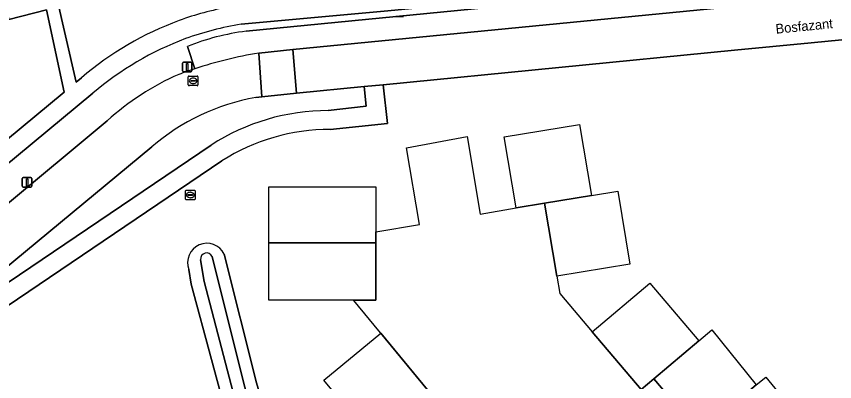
# Model space of a CAD drawing. Extents: x 156661 to 157576, y 383570 to 384425.
# Drawn here: x 156830 to 156914.8, y 383880.2 to 383918.1 of the extents above; entities that cross this region are included whole.
import ezdxf

# ---------------------------------------------------------------- set-up
doc = ezdxf.new("R2010")
doc.units = 0
for name, color, linetype in [('IMGEO_Berm_groen', 7, 'Continuous'), ('IMGEO_Groenvoorziening', 7, 'Continuous'), ('IMGEO_Lichtmast', 7, 'Continuous'), ('IMGEO_Oever', 7, 'Continuous'), ('IMGEO_Openbare_ruimte_label', 7, 'Continuous'), ('IMGEO_Pand_vergunning_verleend', 7, 'Continuous'), ('IMGEO_Parkeervlak_open', 7, 'Continuous'), ('IMGEO_Rijbaan_lokaal_open', 7, 'Continuous'), ('IMGEO_Rioolput', 7, 'Continuous'), ('IMGEO_Voetpad_gesloten', 7, 'Continuous'), ('IMGEO_Voetpad_open', 7, 'Continuous'), ('IMGEO_Waterloop', 7, 'Continuous')]:
    doc.layers.add(name, color=color, linetype=linetype)

msp = doc.modelspace()

# ---------------------------------------------------------------- linework, layer by layer
at = {"layer": 'IMGEO_Berm_groen'}
for points in [[(156853.805, 383916.581), (156939.653, 383925.02), (156939.883, 383922.625), (156942.261, 383922.858), (156942.029, 383925.893), (156868.496, 383918.711), (156853.282, 383917.324)], [(156848.489, 383912.685), (156847.704, 383914.986)], [(156862.309, 383908.349), (156866.252, 383908.792), (156866.027, 383910.844), (156859.004, 383910.155), (156855.44, 383909.783), (156854.801, 383909.693)], [(156837.91, 383910.165), (156822.254, 383897.18)], [(156828.657, 383898.337), (156839.395, 383907.281)], [(156819.797, 383884.223), (156850.165, 383904.772)], [(156844.018, 383904.581), (156820.237, 383884.885)]]:
    msp.add_lwpolyline(points, dxfattribs=at)
for centre, radius, start, end in [((156859.222, 383882.929), 34.904, 99.79783, 109.59833), ((156858.999, 383885.284), 32.616, 110.61694, 130.2839), ((156856.823, 383892.571), 24.199, 97.16439, 112.13775), ((156862.742, 383869.358), 45.611, 108.20873, 110.4265), ((156857.829, 383887.006), 27.403, 113.68148, 132.27728), ((156858.547, 383887.863), 22.149, 99.73687, 130.99248), ((156862.297, 383885.988), 22.361, 89.96818, 122.85636)]:
    msp.add_arc(centre, radius, start, end, dxfattribs=at)
at = {"layer": 'IMGEO_Groenvoorziening'}
for points in [[(156823.818, 383940.987), (156833.736, 383943.193), (156833.955, 383942.205), (156836.909, 383942.836), (156838.218, 383936.976), (156838.514, 383935.647), (156839.821, 383929.794), (156840.117, 383928.468), (156841.425, 383922.608), (156839.83, 383922.252), (156839.933, 383921.788), (156834.083, 383920.486), (156836.167, 383911.298), (156836.719, 383911.755)], [(156960.429, 383920.102), (156912.352, 383915.387), (156904.417, 383914.609), (156867.996, 383911.037), (156868.437, 383907.016), (156862.509, 383906.391)], [(156820.131, 383898.001), (156834.922, 383910.265), (156833.107, 383918.804), (156829.202, 383917.794), (156823.434, 383916.512), (156820.398, 383915.844), (156817.468, 383915.2), (156816.817, 383918.128), (156816.732, 383918.51), (156810.873, 383917.164), (156812.023, 383911.93), (156814.996, 383912.584), (156815.273, 383911.078), (156812.396, 383910.435), (156812.552, 383909.758)], [(156851.293, 383903.131), (156818.935, 383881.258)], [(156851.524, 383893.461), (156854.87, 383880.095), (156855.954, 383876.481), (156875.133, 383855.234), (156891.457, 383836.513), (156911.625, 383812.792), (156912.799, 383811.318), (156913.716, 383811.623), (156932.366, 383827.967), (156950.379, 383842.94), (156962.3, 383852.372), (156962.639, 383852.867), (156967.115, 383858.578), (156983.419, 383879.381)], [(156930.606, 383784.803), (156881.087, 383841.394), (156853.843, 383872.65), (156852.3, 383874.708), (156848.113, 383890.33), (156847.869, 383891.869)]]:
    msp.add_lwpolyline(points, dxfattribs=at)
for centre, radius, start, end in [((156857.204, 383889.617), 29.92, 100.03858, 110.20436), ((156858.538, 383886.116), 33.666, 110.27555, 130.39721), ((156862.399, 383885.846), 20.545, 89.69244, 122.72123), ((156849.728, 383892.592), 1.995, 25.82674, 201.24604)]:
    msp.add_arc(centre, radius, start, end, dxfattribs=at)
at = {"layer": 'IMGEO_Lichtmast'}
for p, q in [((156870.101, 383918.123), (156869.311, 383918.123)), ((156869.311, 383918.123), (156870.101, 383918.123)), ((156847.19, 383912.458), (156847.19, 383913.258)), ((156847.19, 383913.258), (156847.19, 383912.458)), ((156847.29, 383913.358), (156848.08, 383913.358)), ((156848.08, 383913.358), (156847.29, 383913.358)), ((156848.18, 383913.258), (156848.18, 383912.458)), ((156848.18, 383912.458), (156848.18, 383913.258)), ((156848.08, 383912.358), (156847.29, 383912.358)), ((156847.29, 383912.358), (156848.08, 383912.358)), ((156830.701, 383901.394), (156831.491, 383901.394)), ((156831.491, 383901.394), (156830.701, 383901.394)), ((156830.601, 383900.494), (156830.601, 383901.294)), ((156830.601, 383901.294), (156830.601, 383900.494)), ((156831.591, 383901.294), (156831.591, 383900.494)), ((156831.591, 383900.494), (156831.591, 383901.294)), ((156831.491, 383900.394), (156830.701, 383900.394)), ((156830.701, 383900.394), (156831.491, 383900.394))]:
    msp.add_line(p, q, dxfattribs=at)
for points in [[(156847.61, 383913.233), (156847.76, 383913.233), (156847.76, 383912.483), (156847.61, 383912.483), (156847.61, 383913.233)], [(156831.021, 383901.269), (156831.171, 383901.269), (156831.171, 383900.519), (156831.021, 383900.519), (156831.021, 383901.269)]]:
    msp.add_lwpolyline(points, dxfattribs=at)
for centre, start, end in [((156847.29, 383913.258), 90, 180), ((156847.29, 383913.258), 90, 180), ((156848.08, 383913.258), 0, 90), ((156848.08, 383913.258), 360, 90), ((156847.29, 383912.458), 180, 270), ((156847.29, 383912.458), 180, 270), ((156848.08, 383912.458), 270, 0), ((156848.08, 383912.458), 270, 0), ((156830.701, 383901.294), 90, 180), ((156830.701, 383901.294), 90, 180), ((156831.491, 383901.294), 0, 90), ((156831.491, 383901.294), 360, 90), ((156830.701, 383900.494), 180, 270), ((156830.701, 383900.494), 180, 270), ((156831.491, 383900.494), 270, 0), ((156831.491, 383900.494), 270, 0)]:
    msp.add_arc(centre, 0.1, start, end, dxfattribs=at)
at = {"layer": 'IMGEO_Oever'}
for points in [[(156931.624, 383785.153), (156882.046, 383842.232), (156854.834, 383873.451), (156853.466, 383875.275), (156849.461, 383890.631), (156849.071, 383892.878)], [(156850.277, 383893.203), (156853.642, 383879.757), (156854.817, 383875.841), (156874.18, 383854.389), (156890.492, 383835.682), (156910.642, 383811.983), (156912.357, 383809.829), (156914.362, 383810.496), (156933.193, 383826.998), (156951.181, 383841.951), (156963.242, 383851.493), (156963.694, 383852.153)], [(156983.419, 383879.381), (156967.115, 383858.578), (156962.639, 383852.867), (156962.3, 383852.372), (156950.379, 383842.94), (156932.366, 383827.967), (156913.716, 383811.623), (156912.799, 383811.318), (156911.625, 383812.792), (156891.457, 383836.513), (156875.133, 383855.234), (156855.954, 383876.481), (156854.87, 383880.095), (156851.524, 383893.461)], [(156847.869, 383891.869), (156848.113, 383890.33), (156852.3, 383874.708), (156853.843, 383872.65), (156881.087, 383841.394), (156930.606, 383784.803)]]:
    msp.add_lwpolyline(points, dxfattribs=at)
for centre, radius, start, end in [((156849.728, 383892.592), 1.995, 25.82674, 201.24604), ((156849.698, 383892.95), 0.631, 23.60093, 186.56331)]:
    msp.add_arc(centre, radius, start, end, dxfattribs=at)
at = {"layer": 'IMGEO_Pand_vergunning_verleend'}
for points in [[(156889.575, 383899.545), (156884.73, 383898.741), (156881.774, 383898.251), (156880.551, 383905.617), (156888.353, 383906.912)], [(156867.243, 383894.637), (156856.147, 383894.637), (156856.147, 383900.425), (156867.243, 383900.425)], [(156884.73, 383898.741), (156889.575, 383899.545), (156892.303, 383899.998), (156893.56, 383892.425), (156885.987, 383891.168)], [(156856.147, 383894.637), (156867.243, 383894.637), (156867.243, 383888.675), (156856.147, 383888.675)], [(156900.701, 383884.465), (156896.064, 383880.542), (156894.724, 383879.407), (156889.666, 383885.384), (156895.643, 383890.442)], [(156872.604, 383879.4), (156866.718, 383874.494), (156861.852, 383880.383), (156867.759, 383885.264)], [(156906.666, 383879.89), (156900.827, 383874.914), (156896.064, 383880.542), (156900.701, 383884.465), (156902.046, 383885.604)], [(156909.131, 383874.358), (156903.349, 383869.308), (156899.532, 383873.818), (156900.827, 383874.914), (156906.666, 383879.89), (156907.672, 383880.703), (156911.35, 383876.152)]]:
    msp.add_lwpolyline(points, close=True, dxfattribs=at)
msp.add_lwpolyline([(156872.604, 383879.4), (156864.962, 383888.649), (156867.243, 383888.675), (156867.243, 383895.764), (156871.762, 383896.537), (156870.401, 383904.492), (156876.696, 383905.65), (156878.055, 383897.614), (156881.774, 383898.251), (156884.73, 383898.741), (156885.987, 383891.168), (156886.292, 383889.368), (156889.666, 383885.384), (156894.724, 383879.407), (156896.064, 383880.542), (156900.827, 383874.914)], dxfattribs=at)
at = {"layer": 'IMGEO_Parkeervlak_open'}
for points in [[(156855.097, 383914.318), (156858.629, 383914.671), (156939.883, 383922.625), (156939.653, 383925.02), (156853.805, 383916.581)], [(156847.704, 383914.986), (156848.489, 383912.685)]]:
    msp.add_lwpolyline(points, dxfattribs=at)
for centre, radius, start, end in [((156856.823, 383892.571), 24.199, 97.16439, 112.13775), ((156862.607, 383869.742), 45.204, 99.56326, 108.19892)]:
    msp.add_arc(centre, radius, start, end, dxfattribs=at)
at = {"layer": 'IMGEO_Rijbaan_lokaal_open'}
for points in [[(156970.285, 383925.601), (156957.067, 383924.307), (156955.199, 383924.125), (156952.527, 383923.863), (156946.775, 383923.3), (156944.299, 383923.058), (156942.261, 383922.858), (156939.883, 383922.625), (156858.629, 383914.671), (156859.004, 383910.155), (156866.027, 383910.844), (156867.996, 383911.037), (156904.417, 383914.609), (156912.352, 383915.387), (156960.429, 383920.102)], [(156854.801, 383909.693), (156855.44, 383909.783), (156855.097, 383914.318)], [(156839.395, 383907.281), (156828.657, 383898.337), (156814.301, 383887.284), (156819.797, 383884.223)], [(156820.237, 383884.885), (156844.018, 383904.581)]]:
    msp.add_lwpolyline(points, dxfattribs=at)
msp.add_lwpolyline([(156855.44, 383909.783), (156859.004, 383910.155), (156858.629, 383914.671), (156855.097, 383914.318)], close=True, dxfattribs=at)
for centre, radius, start, end in [((156862.607, 383869.742), 45.204, 99.56326, 108.19892), ((156862.742, 383869.358), 45.611, 108.20873, 110.4265), ((156857.829, 383887.006), 27.403, 113.68148, 132.27728), ((156858.547, 383887.863), 22.149, 99.73687, 130.99248)]:
    msp.add_arc(centre, radius, start, end, dxfattribs=at)
at = {"layer": 'IMGEO_Rioolput'}
for p, q in [((156847.802, 383911.008), (156847.802, 383911.86)), ((156847.877, 383911.934), (156848.729, 383911.934)), ((156848.29, 383911.714), (156848.315, 383911.714)), ((156848.803, 383911.86), (156848.803, 383911.008)), ((156848.729, 383910.934), (156847.877, 383910.934)), ((156848.061, 383911.428), (156848.061, 383911.44)), ((156848.499, 383911.391), (156848.101, 383911.391)), ((156848.104, 383911.477), (156848.502, 383911.477)), ((156848.313, 383911.154), (156848.288, 383911.154)), ((156848.545, 383911.44), (156848.545, 383911.428)), ((156847.511, 383899.167), (156847.511, 383900.019)), ((156847.586, 383900.093), (156848.438, 383900.093)), ((156847.999, 383899.873), (156848.024, 383899.873)), ((156848.512, 383900.019), (156848.512, 383899.167)), ((156848.438, 383899.093), (156847.586, 383899.093)), ((156847.77, 383899.587), (156847.77, 383899.599)), ((156848.208, 383899.55), (156847.81, 383899.55)), ((156847.813, 383899.636), (156848.211, 383899.636)), ((156848.022, 383899.313), (156847.997, 383899.313)), ((156848.254, 383899.599), (156848.254, 383899.587))]:
    msp.add_line(p, q, dxfattribs=at)
for points in [[(156847.802, 383911.008), (156847.802, 383911.86)], [(156847.877, 383911.934), (156848.729, 383911.934)], [(156848.803, 383911.86), (156848.803, 383911.008)], [(156848.729, 383910.934), (156847.877, 383910.934)], [(156847.511, 383899.167), (156847.511, 383900.019)], [(156847.586, 383900.093), (156848.438, 383900.093)], [(156848.512, 383900.019), (156848.512, 383899.167)], [(156848.438, 383899.093), (156847.586, 383899.093)]]:
    msp.add_lwpolyline(points, dxfattribs=at)
for centre, radius, start, end in [((156847.879, 383911.858), 0.0765, 91.55205, 178.44795), ((156847.879, 383911.858), 0.0765, 91.55205, 178.44795), ((156848.727, 383911.858), 0.0765, 1.55205, 88.44795), ((156848.727, 383911.858), 0.0765, 1.55205, 88.44795), ((156847.879, 383911.01), 0.0765, 181.55205, 268.44795), ((156847.879, 383911.01), 0.0765, 181.55205, 268.44795), ((156848.101, 383911.437), 0.0403, 85.87752, 175.75265), ((156848.098, 383911.427), 0.0366, 178.93798, 274.71019), ((156848.502, 383911.434), 0.043, 264.86636, 352.45326), ((156848.506, 383911.439), 0.0386, 1.73085, 96.63898), ((156848.727, 383911.01), 0.0765, 271.55205, 358.44795), ((156848.727, 383911.01), 0.0765, 271.55205, 358.44795), ((156847.588, 383900.017), 0.0765, 91.55205, 178.44795), ((156847.588, 383900.017), 0.0765, 91.55205, 178.44795), ((156848.436, 383900.017), 0.0765, 1.55205, 88.44795), ((156848.436, 383900.017), 0.0765, 1.55205, 88.44795), ((156847.588, 383899.169), 0.0765, 181.55205, 268.44795), ((156847.588, 383899.169), 0.0765, 181.55205, 268.44795), ((156847.81, 383899.596), 0.0403, 85.87752, 175.75265), ((156847.807, 383899.586), 0.0366, 178.93798, 274.71019), ((156848.211, 383899.593), 0.043, 264.86636, 352.45326), ((156848.215, 383899.598), 0.0386, 1.73085, 96.63898), ((156848.436, 383899.169), 0.0765, 271.55205, 358.44795), ((156848.436, 383899.169), 0.0765, 271.55205, 358.44795)]:
    msp.add_arc(centre, radius, start, end, dxfattribs=at)
for centre, major_axis, ratio, start_param, end_param in [((156848.289, 383911.434), (-0.387, 0.002), 0.722429, 4.712389, 7.853982), ((156848.314, 383911.434), (-0.39, 0.002), 0.717154, 1.570796, 4.712389), ((156847.998, 383899.593), (-0.387, 0.002), 0.722429, 4.712389, 7.853982), ((156848.023, 383899.593), (-0.39, 0.002), 0.717154, 1.570796, 4.712389)]:
    msp.add_ellipse(centre, major_axis=major_axis, ratio=ratio, start_param=start_param, end_param=end_param, dxfattribs=at)
at = {"layer": 'IMGEO_Voetpad_gesloten'}
for points in [[(156868.437, 383907.016), (156867.996, 383911.037), (156866.027, 383910.844), (156866.252, 383908.792), (156862.309, 383908.349)], [(156862.509, 383906.391), (156868.437, 383907.016)], [(156850.165, 383904.772), (156819.797, 383884.223)], [(156818.935, 383881.258), (156851.293, 383903.131)]]:
    msp.add_lwpolyline(points, dxfattribs=at)
for centre, radius, start, end in [((156862.297, 383885.988), 22.361, 89.96818, 122.85636), ((156862.399, 383885.846), 20.545, 89.69244, 122.72123)]:
    msp.add_arc(centre, radius, start, end, dxfattribs=at)
at = {"layer": 'IMGEO_Voetpad_open'}
for points in [[(156853.282, 383917.324), (156868.496, 383918.711), (156942.029, 383925.893), (156944.032, 383926.112), (156952.092, 383926.89), (156954.952, 383927.178), (156958.753, 383927.533), (156959.604, 383929.198), (156956.799, 383928.862), (156955.061, 383936.102)], [(156836.719, 383911.755), (156836.167, 383911.298), (156834.083, 383920.486), (156828.862, 383919.324), (156829.202, 383917.794), (156833.107, 383918.804), (156834.922, 383910.265), (156820.131, 383898.001)], [(156822.254, 383897.18), (156837.91, 383910.165)]]:
    msp.add_lwpolyline(points, dxfattribs=at)
for centre, radius, start, end in [((156857.204, 383889.617), 29.92, 100.03858, 110.20436), ((156858.538, 383886.116), 33.666, 110.27555, 130.39721), ((156859.222, 383882.929), 34.904, 99.79783, 109.59833), ((156858.999, 383885.284), 32.616, 110.61694, 130.2839)]:
    msp.add_arc(centre, radius, start, end, dxfattribs=at)
at = {"layer": 'IMGEO_Waterloop'}
for points in [[(156849.071, 383892.878), (156849.461, 383890.631), (156853.466, 383875.275), (156854.834, 383873.451), (156882.046, 383842.232), (156931.624, 383785.153)], [(156984.636, 383878.717), (156967.573, 383857.073), (156963.694, 383852.153), (156963.242, 383851.493), (156951.181, 383841.951), (156933.193, 383826.998), (156914.362, 383810.496), (156912.357, 383809.829), (156910.642, 383811.983), (156890.492, 383835.682), (156874.18, 383854.389), (156854.817, 383875.841), (156853.642, 383879.757), (156850.277, 383893.203)]]:
    msp.add_lwpolyline(points, dxfattribs=at)
msp.add_arc((156849.698, 383892.95), 0.631, 23.60093, 186.56331, dxfattribs=at)

# ---------------------------------------------------------------- texts
at = {"layer": 'IMGEO_Openbare_ruimte_label'}
msp.add_text('Bosfazant', height=1, rotation=5.62506, dxfattribs=at).set_placement((156908.716, 383916.319))

doc.saveas('drawing.dxf')
